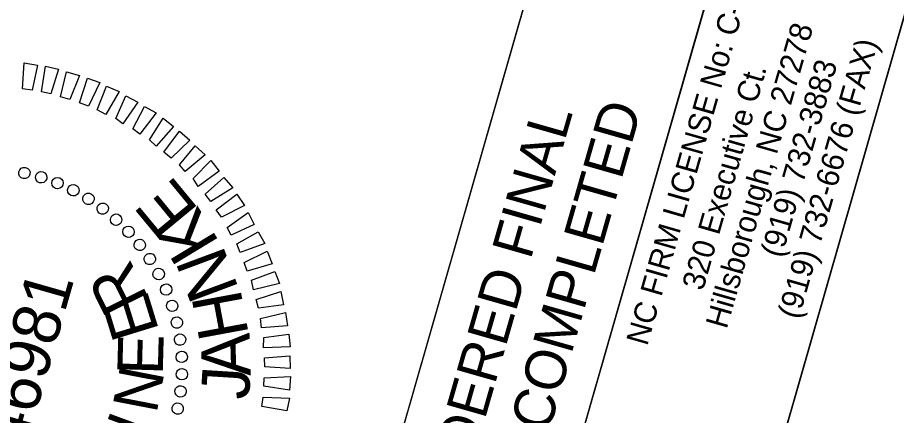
# Model space of a CAD drawing. Extents: x 2096093 to 2098911, y 683546 to 689764.
# Drawn here: x 2097575.6 to 2097686.4, y 689477.1 to 689527.3 of the extents above; entities that cross this region are included whole.
import ezdxf

# ---------------------------------------------------------------- set-up
doc = ezdxf.new("R2010")
doc.units = 0
for name, color, linetype in [('Old_Level_2', 7, 'Continuous'), ('Scratch_Level_5', 7, 'Continuous'), ('Sheet Block Title CELL', 7, 'Continuous'), ('Sheet PE Seal Cell', 7, 'Continuous'), ('Sheet Sticker Exception Certification CELL', 7, 'Continuous')]:
    doc.layers.add(name, color=color, linetype=linetype)

msp = doc.modelspace()

# ---------------------------------------------------------------- linework, layer by layer
at = {"layer": 'Old_Level_2'}
msp.add_lwpolyline([(2097489.39, 689409.44), (2097540.86, 689589.16), (2097647.94, 689558.5), (2097596.47, 689378.78)], close=True, dxfattribs=at)
msp.add_lwpolyline([(2097489.39, 689409.44), (2097540.86, 689589.16), (2097647.94, 689558.5), (2097596.47, 689378.78)], close=True, dxfattribs=at)
at = {"layer": 'Scratch_Level_5'}
msp.add_lwpolyline([(2098117.81, 688054.49), (2097347.73, 688084.03), (2097057.83, 688167.01), (2097419.22, 689429.54), (2097641.13, 689365.99), (2097692.54, 689545.54), (2098409.79, 689340.16), (2098316.63, 689014.71), (2098387.02, 688994.56)], close=True, dxfattribs=at)
at = {"layer": 'Sheet Block Title CELL'}
msp.add_lwpolyline([(2097617.56, 689372.74), (2097668.98, 689552.29), (2097692.54, 689545.54), (2097641.13, 689365.99)], close=True, dxfattribs=at)
at = {"layer": 'Sheet PE Seal Cell'}
for p, q in [((2097576.44, 689507.7), (2097576.44, 689507.7)), ((2097578.57, 689507.15), (2097578.57, 689507.15)), ((2097580.64, 689506.4), (2097580.64, 689506.4)), ((2097582.61, 689505.47), (2097582.61, 689505.47)), ((2097584.5, 689504.46), (2097584.5, 689504.46)), ((2097586.33, 689503.21), (2097586.33, 689503.21)), ((2097588.01, 689501.79), (2097588.01, 689501.79)), ((2097589.61, 689500.29), (2097589.61, 689500.29)), ((2097590.99, 689498.6), (2097590.99, 689498.6)), ((2097592.3, 689496.82), (2097592.3, 689496.82)), ((2097593.38, 689494.95), (2097593.38, 689494.95)), ((2097594.37, 689492.95), (2097594.37, 689492.95)), ((2097595.09, 689490.92), (2097595.09, 689490.92)), ((2097595.67, 689488.78), (2097595.67, 689488.78)), ((2097596.1, 689486.63), (2097596.1, 689486.63)), ((2097596.31, 689484.49), (2097596.31, 689484.49)), ((2097596.31, 689482.3), (2097596.31, 689482.3)), ((2097596.09, 689480.08), (2097596.09, 689480.08)), ((2097595.79, 689477.93), (2097595.79, 689477.93))]:
    msp.add_line(p, q, dxfattribs=at)
for points in [[(2097576.19, 689518.28), (2097576.41, 689521.6), (2097578.08, 689521.27), (2097577.4, 689518.14)], [(2097578.58, 689517.91), (2097579.09, 689521.14), (2097580.75, 689520.77), (2097579.76, 689517.67)], [(2097580.99, 689517.27), (2097581.74, 689520.43), (2097583.38, 689519.97), (2097582.15, 689516.94)], [(2097583.38, 689516.53), (2097584.38, 689519.63), (2097585.93, 689519.08), (2097584.51, 689516.11)], [(2097585.62, 689515.63), (2097586.79, 689518.62), (2097588.37, 689517.96), (2097586.71, 689515.06)], [(2097587.96, 689514.54), (2097589.2, 689517.41), (2097590.74, 689516.61), (2097588.86, 689513.87)], [(2097590.09, 689513.26), (2097591.57, 689516.06), (2097593.06, 689515.27), (2097590.99, 689512.59)], [(2097592.19, 689511.88), (2097593.91, 689514.61), (2097595.22, 689513.56), (2097593.05, 689511.06)], [(2097594.03, 689510.31), (2097595.99, 689512.97), (2097597.28, 689511.83), (2097594.95, 689509.53)], [(2097595.97, 689508.72), (2097597.96, 689511.11), (2097599.24, 689509.96), (2097596.72, 689507.88)], [(2097597.71, 689506.97), (2097599.92, 689509.25), (2097600.99, 689507.9), (2097598.35, 689505.95)], [(2097599.22, 689504.98), (2097601.59, 689507.11), (2097602.73, 689505.79), (2097599.95, 689504.09)], [(2097600.63, 689503.01), (2097603.22, 689504.98), (2097604.17, 689503.56), (2097601.3, 689502.09)], [(2097601.98, 689500.81), (2097604.65, 689502.7), (2097605.41, 689501.18), (2097602.52, 689499.82)], [(2097603.2, 689498.74), (2097605.92, 689500.25), (2097606.75, 689498.77), (2097603.62, 689497.63)], [(2097604.14, 689496.39), (2097607.04, 689497.8), (2097607.68, 689496.21), (2097604.51, 689495.3)], [(2097605.06, 689494.15), (2097608.02, 689495.23), (2097608.58, 689493.72), (2097605.34, 689492.93)], [(2097605.66, 689491.69), (2097608.76, 689492.73), (2097609.11, 689491.02), (2097605.97, 689490.61)], [(2097606.22, 689489.3), (2097609.35, 689490.06), (2097609.6, 689488.38), (2097606.35, 689488.11)], [(2097606.62, 689486.89), (2097609.77, 689487.34), (2097609.93, 689485.74), (2097606.57, 689485.61)], [(2097606.72, 689484.32), (2097609.92, 689484.6), (2097609.93, 689482.98), (2097606.77, 689483.21)], [(2097606.68, 689481.83), (2097610, 689481.97), (2097609.87, 689480.24), (2097606.64, 689480.75)], [(2097606.55, 689479.37), (2097609.85, 689479.26), (2097609.54, 689477.63), (2097606.37, 689478.18)]]:
    msp.add_lwpolyline(points, close=True, dxfattribs=at)
for centre, major_axis in [((2097576.43, 689507.67), (0.149, 0.704)), ((2097578.55, 689507.13), (0.21, 0.689)), ((2097580.61, 689506.4), (0.269, 0.668)), ((2097582.6, 689505.49), (0.327, 0.642)), ((2097584.51, 689504.41), (0.381, 0.611)), ((2097586.31, 689503.17), (0.433, 0.575)), ((2097588, 689501.78), (0.482, 0.535)), ((2097589.56, 689500.25), (0.526, 0.491)), ((2097590.98, 689498.59), (0.567, 0.444)), ((2097592.25, 689496.81), (0.604, 0.392)), ((2097593.36, 689494.92), (0.636, 0.338)), ((2097594.31, 689492.95), (0.663, 0.282)), ((2097595.07, 689490.9), (0.685, 0.223)), ((2097595.66, 689488.79), (0.701, 0.162)), ((2097596.06, 689486.64), (0.713, 0.101)), ((2097596.27, 689484.46), (0.719, 0.038)), ((2097596.29, 689482.27), (0.72, -0.025)), ((2097596.12, 689480.09), (0.715, -0.087)), ((2097595.76, 689477.93), (0.704, -0.149))]:
    msp.add_ellipse(centre, major_axis=major_axis, ratio=0.999708, dxfattribs=at)
at = {"layer": 'Sheet Sticker Exception Certification CELL'}
for p, q in [((2097596.47, 689378.78), (2097647.89, 689558.33)), ((2097596.47, 689378.78), (2097647.89, 689558.33)), ((2097668.98, 689552.29), (2097617.56, 689372.74)), ((2097668.98, 689552.29), (2097617.56, 689372.74))]:
    msp.add_line(p, q, dxfattribs=at)

# ---------------------------------------------------------------- texts
at = {"layer": 'Sheet Block Title CELL'}
for s, p in [('NC FIRM LICENSE No: C-5176', (2097654.97, 689485.75)), ('Hillsborough, NC 27278', (2097664.99, 689487.88)), ('(919) 732-6676 (FAX)', (2097674.08, 689489.11)), ('(919) 732-3883', (2097671.93, 689496.86)), ('320 Executive Ct.', (2097662, 689492.71))]:
    msp.add_text(s, height=2.8015, rotation=74.0199, dxfattribs=at).set_placement(p)
at = {"layer": 'Sheet PE Seal Cell'}
for s, height, rotation, p in [('E', 6.29, 129.5189, (2097598.54, 689502.99)), ('K', 6.35, 121.235, (2097601.11, 689498.85)), ('N', 6.35, 110.5092, (2097603.51, 689493.01)), ('R', 5.98, 116.5073, (2097592.17, 689491.81)), ('046981', 5.998, 74.0259, (2097575.35, 689468.46)), ('E', 5.96, 107.15, (2097593.45, 689487.75)), ('H', 6.27, 100.5252, (2097604.74, 689487.27)), ('E', 5.74, 88.4377, (2097593.87, 689482.12)), ('A', 6.15, 91.6849, (2097604.97, 689482.07)), ('N', 5.65, 79.0823, (2097593.08, 689477.19)), ('J', 6.08, 86.427, (2097604.73, 689478.98)), ('I', 5.65, 69.7271, (2097592.02, 689474.01))]:
    msp.add_text(s, height=height, rotation=rotation, dxfattribs=at).set_placement(p)
at = {"layer": 'Sheet Sticker Exception Certification CELL'}
for s, p in [('UNLESS ALL SIGNATURES COMPLETED', (2097617.77, 689388.22)), ('UNLESS ALL SIGNATURES COMPLETED', (2097617.77, 689388.22)), ('DOCUMENT NOT CONSIDERED FINAL', (2097611.17, 689395.03)), ('DOCUMENT NOT CONSIDERED FINAL', (2097611.17, 689395.03))]:
    msp.add_text(s, height=5.135, rotation=74.0199, dxfattribs=at).set_placement(p)

doc.saveas('drawing.dxf')
